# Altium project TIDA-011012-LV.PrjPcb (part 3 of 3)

## Sheet TIDA-011012-LV Hardware.SchDoc
size 431 x 279 mm; Date: Not shown in title block; ApprovedBy: Not shown in title block; CheckedBy: Not shown in title block; Author: Not shown in title block; CompanyName: Not shown in title block; Engineer: Not shown in title block; Organization: Not shown in title block; Address1: Not shown in title block; Address2: Not shown in title block; Address3: Not shown in title block; Address4: Not shown in title block; DocumentNumber: 4; Revision: Use project parameter SCH_Rev; SheetNumber: 4; SheetTotal: 10; PageSetup: Record=PageOptions¦CenterHorizontal=True¦CenterVertical=True¦PrintScale=1.00¦XCorrection=1.00¦YCorrection=1.00¦PrintKind=0¦BorderSize=5000000¦LeftOffset=0¦BottomOffset=0¦Orientation=2¦PaperLength=1000¦PaperWidth=1000¦Scale=100¦PaperSource=15¦PrintQuality=600¦MediaType=1¦DitherType=10¦PaperKind=Letter¦PrintScaleMode=1
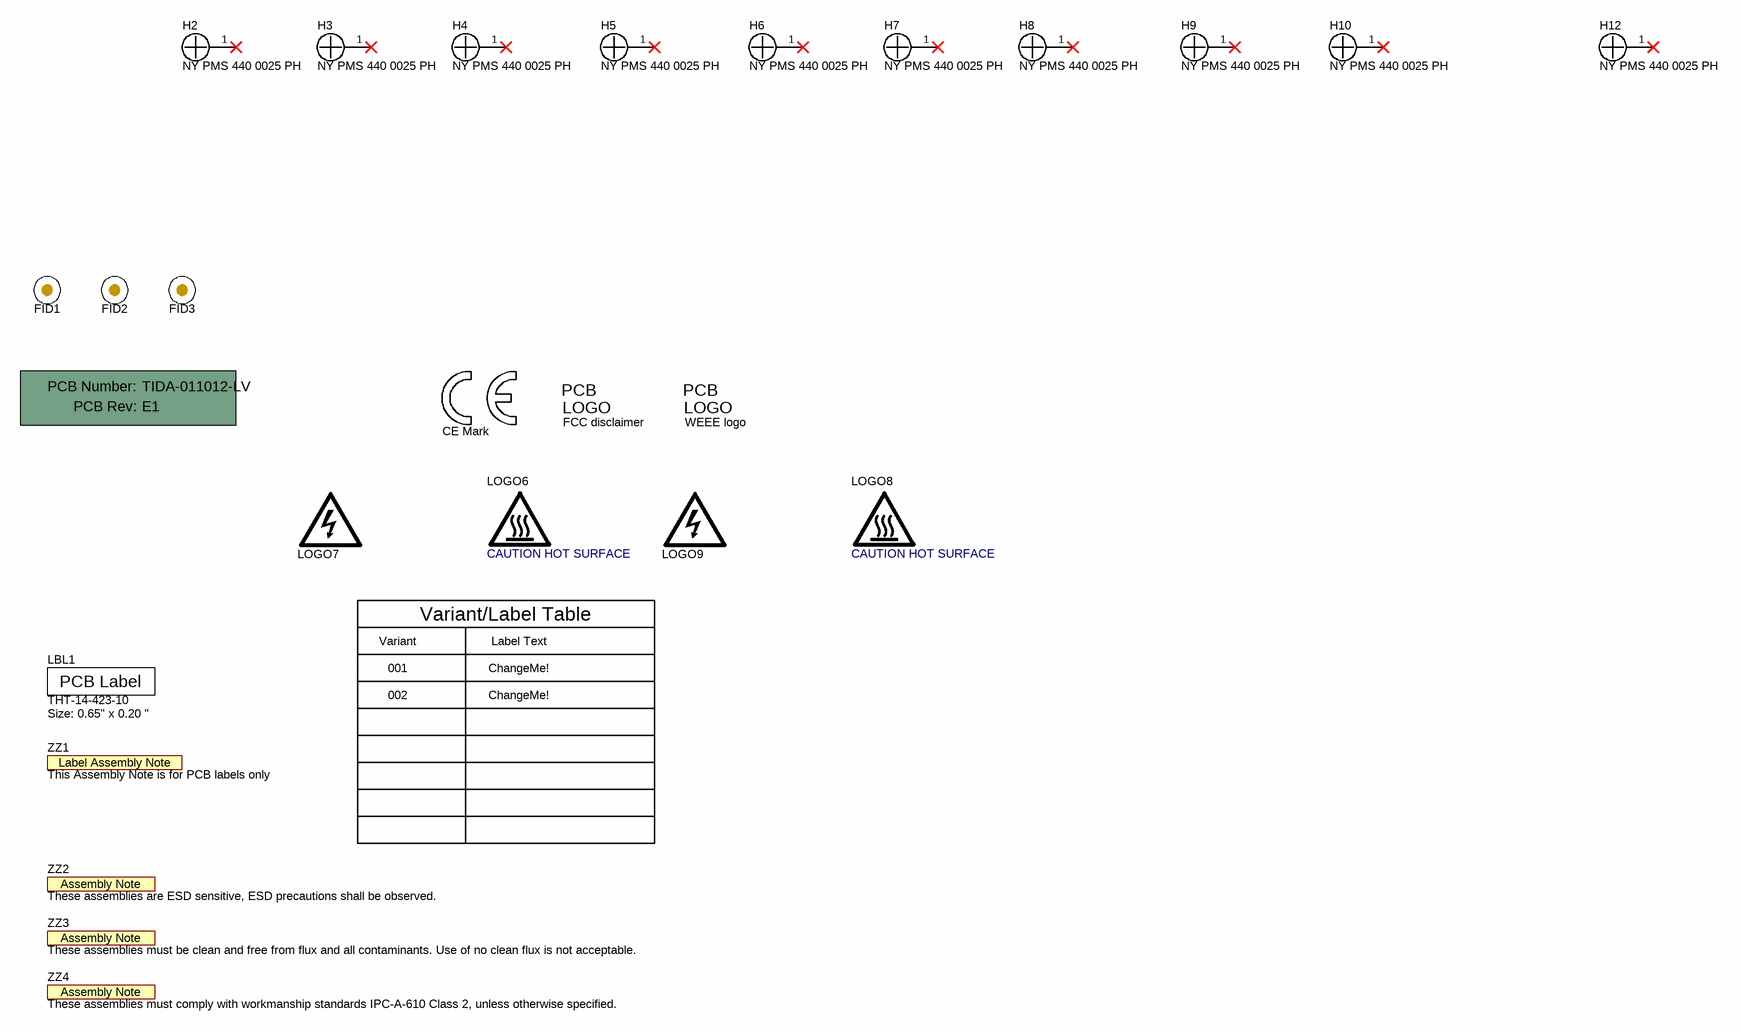
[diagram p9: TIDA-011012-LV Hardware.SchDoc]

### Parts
!PCB1  Printed Circuit Board  (value not drawn)  (mechanical)
FID1  Fiducial  [Fiducial10-20]  (value not drawn)
FID2  Fiducial  [Fiducial10-20]  (value not drawn)
FID3  Fiducial  [Fiducial10-20]  (value not drawn)
H2  NY PMS 440 0025 PH  [NY PMS 440 0025 PH]
H3  NY PMS 440 0025 PH  [NY PMS 440 0025 PH]
H4  NY PMS 440 0025 PH  [NY PMS 440 0025 PH]
H5  NY PMS 440 0025 PH  [NY PMS 440 0025 PH]
H6  NY PMS 440 0025 PH  [NY PMS 440 0025 PH]
H7  NY PMS 440 0025 PH  [NY PMS 440 0025 PH]
H8  NY PMS 440 0025 PH  [NY PMS 440 0025 PH]
H9  NY PMS 440 0025 PH  [NY PMS 440 0025 PH]
H10  NY PMS 440 0025 PH  [NY PMS 440 0025 PH]
H12  NY PMS 440 0025 PH  [NY PMS 440 0025 PH]
LBL1  THT-14-423-10  Note: Size: 0.65" x 0.20 "  [Label_650x200]
Logo1  CE Mark  [CE_Mark_5mm]  (no BOM)
Logo3  FCC disclaimer  [FCC_disclaimer]  (no BOM)
Logo4  WEEE logo  [WEEE_Minimum]  (no BOM)
LOGO6  CAUTION HOT SURFACE  [IEC_HotSurface_Medium]  (no BOM)
LOGO7  DANGER HIGH VOLTAGE  [IEC_HighVoltage_Medium]  (value not drawn)  (no BOM)
LOGO8  CAUTION HOT SURFACE  [IEC_HotSurface_Medium]  (no BOM)
LOGO9  DANGER HIGH VOLTAGE  [IEC_HighVoltage_Medium]  (value not drawn)  (no BOM)
ZZ1  This Assembly Note is for PCB labels only  [AssemblyNoteLabel]  (no BOM)
ZZ2  These assemblies are ESD sensitive, ESD precautions shall be observed.  [AssemblyNote]  (no BOM)
ZZ3  These assemblies must be clean and free from flux and all contaminants. Use of no clean flux is not acceptable.  [AssemblyNote]  (no BOM)
ZZ4  These assemblies must comply with workmanship standards IPC-A-610 Class 2, unless otherwise specified.  [AssemblyNote]  (no BOM)

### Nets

Not connected (* = marked no-connect by the designer): H2 1*; H3 1*; H4 1*; H5 1*; H6 1*; H7 1*; H8 1*; H9 1*; H10 1*; H12 1*

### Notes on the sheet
- Variant
- Variant/Label Table
- Label Text
- 001
- 002
- ChangeMe!

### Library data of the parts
!PCB1 = CMP-0003618-2: Manufacturer: Any; PartNumber: TIDA-011012-LV
FID1-FID3 = CMP-0077181-1: Fiducial mark.  There is nothing to buy or mount.
H2-H10 H12 = CMP-0003617-1: Machine Screw, Round, #4-40 x 1/4, Nylon, Philips panhead; Manufacturer: B&F Fastener Supply; CompType: Hardware
LBL1 = CMP-0003625-1: Thermal Transfer Printable Labels, 0.650" W x 0.200" H - 10,000 per roll; Manufacturer: Brady; CompType: Label
Logo1 = CMP-0074844-1: SymbolCreator: a0412235
Logo3 = CMP-0074847-1: FCC_disclaimer; Library Reference: Logo
Logo4 = CMP-0074769-1
LOGO6 LOGO8 = CMP-0074837-2: IEC 61010-1 Hot Surface Warning; Manufacturer: Texas Instruments; SymbolCreator: a0412235; AEC Category: Q200; CompType: IC
LOGO7 LOGO9 = CMP-0074835-1: IEC 61010-1 High Voltage Warning; SymbolCreator: a0412235; Lib Reference: IEC_HighVoltage
ZZ1 = CMP-0003616-3
ZZ2 = CMP-0077236-1
ZZ3 = CMP-0077237-1
ZZ4 = CMP-0077238-1

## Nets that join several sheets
3V3: TIDA-011012-LV Fans and Temp Sense (7 pins), TIDA-011012-LV Optical Interface (9 pins), TIDA-011012-LV Communication (7 pins), TIDA-011012-LV DC IV Sensing (6 pins), TIDA-011012-LV Current Comparator (C113.1 C114.1 U12.8), TIDA-011012-LV Switch Node Hall Current Sensing (5 pins), TIDA-011012-LV  Auxiliary Power (C66.1 D32.2 TP3.1 U4.5)
5V: TIDA-011012-LV Power Conversion (J15.3 J16.3), TIDA-011012-LV Fans and Temp Sense (C146.1 U29.5), TIDA-011012-LV Optical Interface (9 pins), TIDA-011012-LV Communication (6 pins), TIDA-011012-LV DC IV Sensing (5 pins), TIDA-011012-LV Current Comparator (5 pins), TIDA-011012-LV  Auxiliary Power (8 pins)
12V: TIDA-011012-LV Power Conversion (J15.1 J16.1), TIDA-011012-LV  Auxiliary Power (J20.2)
12V_IN: TIDA-011012-LV Fans and Temp Sense (C122.1 D33.1 J28.2 J29.2), TIDA-011012-LV  Auxiliary Power (14 pins)
GND: TIDA-011012-LV Power Conversion (9 pins), TIDA-011012-LV Fans and Temp Sense (16 pins), TIDA-011012-LV Optical Interface (24 pins), TIDA-011012-LV Communication (49 pins), TIDA-011012-LV DC IV Sensing (16 pins), TIDA-011012-LV Current Comparator (12 pins), TIDA-011012-LV Switch Node Hall Current Sensing (6 pins), TIDA-011012-LV  Auxiliary Power (47 pins)
CLK_MOD_DC: TIDA-011012-LV Communication (R106.1), TIDA-011012-LV DC IV Sensing (R154.2 U6.7 U7.7)
DATA_I_DC: TIDA-011012-LV Communication (R100.1), TIDA-011012-LV DC IV Sensing (C78.1 R153.2)
DATA_V_DC: TIDA-011012-LV Communication (R105.1), TIDA-011012-LV DC IV Sensing (C87.1 R163.2)
DC_BUF_PMW1: TIDA-011012-LV Power Conversion (J15.2), TIDA-011012-LV Communication (R112.2)
DC_BUF_PMW2: TIDA-011012-LV Power Conversion (J15.4), TIDA-011012-LV Communication (R111.2)
DC_BUF_PMW3: TIDA-011012-LV Power Conversion (J16.2), TIDA-011012-LV Communication (R117.2)
DC_BUF_PMW4: TIDA-011012-LV Power Conversion (J16.4), TIDA-011012-LV Communication (R114.2)
DC_DAB: TIDA-011012-LV Power Conversion (18 pins), TIDA-011012-LV DC IV Sensing (18 pins), TIDA-011012-LV  Auxiliary Power (6 pins)
DC_FAULT_FET1: TIDA-011012-LV Power Conversion (J15.6), TIDA-011012-LV Communication (R57.2)
DC_FAULT_FET2: TIDA-011012-LV Power Conversion (J15.8), TIDA-011012-LV Communication (R68.2)
DC_FAULT_FET3: TIDA-011012-LV Power Conversion (J16.6), TIDA-011012-LV Communication (R78.2)
DC_FAULT_FET4: TIDA-011012-LV Power Conversion (J16.8), TIDA-011012-LV Communication (R86.2)
DC_GD_RDY: TIDA-011012-LV Power Conversion (J15.7 J16.7), TIDA-011012-LV Communication (R50.2 R82.1)
DC_GD_RST/EN: TIDA-011012-LV Power Conversion (J15.5 J16.5), TIDA-011012-LV Communication (R83.1)
DC_OC: TIDA-011012-LV Communication (R94.2), TIDA-011012-LV Switch Node Hall Current Sensing (U25.7)
DC_OC_CMP: TIDA-011012-LV Communication (R109.2), TIDA-011012-LV Current Comparator (C116.1 R183.2)
DC_POS: TIDA-011012-LV Power Conversion (20 pins), TIDA-011012-LV DC IV Sensing (R158.1), TIDA-011012-LV  Auxiliary Power (6 pins)
FAN_EN: TIDA-011012-LV Fans and Temp Sense (R187.1), TIDA-011012-LV Communication (R88.1)
FAN_PWM: TIDA-011012-LV Fans and Temp Sense (U29.2), TIDA-011012-LV Communication (R90.1)
FSIRXA_CLK: TIDA-011012-LV Optical Interface (R215.1), TIDA-011012-LV Communication (R71.2)
FSIRXA_D0: TIDA-011012-LV Optical Interface (R216.1), TIDA-011012-LV Communication (R69.2)
FSITXA_CLK: TIDA-011012-LV Optical Interface (C147.1 U26.5), TIDA-011012-LV Communication (R72.1)
FSITXA_D0: TIDA-011012-LV Optical Interface (C149.1 U27.5), TIDA-011012-LV Communication (R70.1)
I_DC_MINUS: TIDA-011012-LV Power Conversion (R41.4), TIDA-011012-LV DC IV Sensing (R152.1)
I_DC_POS: TIDA-011012-LV Power Conversion (R41.3), TIDA-011012-LV DC IV Sensing (R151.1)
I_HALL: TIDA-011012-LV Communication (R44.1), TIDA-011012-LV Switch Node Hall Current Sensing (C160.1 R199.2)
I_HALL_N: TIDA-011012-LV Power Conversion (R43.2), TIDA-011012-LV Switch Node Hall Current Sensing (U25.1)
I_HALL_P: TIDA-011012-LV Power Conversion (5 pins), TIDA-011012-LV Switch Node Hall Current Sensing (U25.2)
I_SW_NEG: TIDA-011012-LV Power Conversion (R43.4), TIDA-011012-LV Current Comparator (13 pins)
I_SW_POS: TIDA-011012-LV Power Conversion (R43.3), TIDA-011012-LV Current Comparator (R182.1)
NTC1_N: TIDA-011012-LV Power Conversion (MD2.T2), TIDA-011012-LV Fans and Temp Sense (R190.2 U16.3)
NTC1_P: TIDA-011012-LV Power Conversion (MD2.T1), TIDA-011012-LV Fans and Temp Sense (R218.1)
PWM_SYNC_RX: TIDA-011012-LV Optical Interface (R217.1), TIDA-011012-LV Communication (R74.2)
PWM_SYNC_TX: TIDA-011012-LV Optical Interface (C151.1 U28.5), TIDA-011012-LV Communication (R73.2)
TEMP1: TIDA-011012-LV Fans and Temp Sense (C124.2 R186.1), TIDA-011012-LV Communication (R85.1)
TEMP2: TIDA-011012-LV Fans and Temp Sense (C127.2 R189.1), TIDA-011012-LV Communication (R56.1)
TEMP3: TIDA-011012-LV Fans and Temp Sense (U16.1 U16.4), TIDA-011012-LV Communication (R77.1)

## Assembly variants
001: not fitted !PCB1 C1 C2 C7 C7 C8 C8 C9 C9 C19 C19 C20 C20 C21 C21 C55 C56 C173 C173 C174 C174 C175 C175 C176 C176 C177 C177 C178 C178 C179 C179 C180 C180 FID1 FID2 FID3 H1 H1 H2 H3 H4 H5 H6 H7 H8 H9 H10 H11 H12 H13 H14 H16 LBL1 Logo1 Logo2 Logo3 Logo4 LOGO6 LOGO7 LOGO8 LOGO9 MD2 U19 U20 U21 U22 U23 U24 ZZ1 ZZ2 ZZ3 ZZ4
